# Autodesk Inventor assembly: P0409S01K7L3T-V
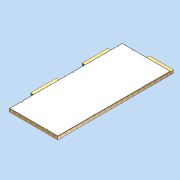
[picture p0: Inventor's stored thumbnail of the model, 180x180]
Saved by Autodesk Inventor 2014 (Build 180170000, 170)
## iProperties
Created: 2011-04
Part Number: P0409S01K7L3T-V
Document SubType Name: Assembly
Designer: david.appleford
Description: 1w x 2.25w 01 Panel - 7 Locks 3 Lugs
Mass: 49000 g
Surface Area: 72966.3 cm^2
Volume: 254072 cm^3
Density: 0.192858 g/cm^3
Cost Center: £161.00
Justset: False
Title: 1w x 2.25w  01 Panel - 7 Locks 3 Lugs
Author: david.appleford
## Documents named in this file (4)
- C:\Documents and Settings\john.everitt\Local Settings\My Documents\Vault\Production MkII\VIRTUAL ELEMENTS\Virtual Walls\Virtual Timber + MgO\P0409S01K7L3T-V.iam
- C:\Documents and Settings\john.everitt\Local Settings\My Documents\Vault\Production MkII\VIRTUAL ELEMENTS\Virtual Lugs\Superceded Lugs\LA02C3V.ipt
- C:\Documents and Settings\john.everitt\Local Settings\My Documents\Vault\Production MkII\VIRTUAL ELEMENTS\Virtual Lugs\Superceded Lugs\LA02M3V.ipt
- C:\Documents and Settings\john.everitt\Local Settings\My Documents\Vault\Production MkII\Virtual Elements\Virtual Walls\Virtual Timber + MgO\P0409S01K7-V.ipt
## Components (4 placed, 3 different names)
1. P0409S01K7-V:1 — Mate:4, Flush:7, Flush:8, Mate:5, Mate:6, Flush:9, Flush:10
2. LA02C3V:3 — Mate:4, Flush:7, Flush:8
3. LA02M3V:5 — Mate:6, Flush:9, Mate:12
4. LA02M3V:2 — Mate:5, Flush:10, Mate:12
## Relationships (8: Mate 4, Flush 4)
- Mate:4: P0409S01K7-V:1 ↔ LA02C3V:3
- Flush:7: P0409S01K7-V:1 ↔ LA02C3V:3
- Flush:8: P0409S01K7-V:1 ↔ LA02C3V:3
- Mate:5: P0409S01K7-V:1 ↔ LA02M3V:2
- Mate:6: P0409S01K7-V:1 ↔ LA02M3V:5
- Flush:9: P0409S01K7-V:1 ↔ LA02M3V:5
- Flush:10: P0409S01K7-V:1 ↔ LA02M3V:2
- Mate:12: LA02M3V:5 ↔ LA02M3V:2
## Named parameters: t = 1 mm, Cl = 2 mm
